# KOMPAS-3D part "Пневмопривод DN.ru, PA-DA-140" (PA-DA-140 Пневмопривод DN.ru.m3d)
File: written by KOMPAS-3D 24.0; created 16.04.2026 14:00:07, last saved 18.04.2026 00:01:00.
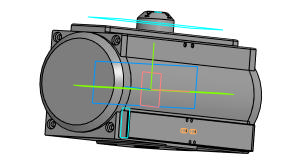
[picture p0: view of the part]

Document properties: Автор: DN.ru; Полное имя файла: C:\Работа\PA-DA-х Пневмопривод DN.ru\140\исходные материалы\PA-DA-140 Пневмопривод DN.ru.m3d

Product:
- Body: Тело 1  | qty 1
    Масса: 67.196724
- Body: Тело 2  | qty 1
    Масса: 67.196724
- Part/product: Пневмопривод DN.ru  | designation PA-DA-140
    Масса: 13
    Раздел спецификации: Прочие изделия
    Примечание: D290-00298

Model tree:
1. Эскиз:1
2. Элемент выдавливания:1
3. Эскиз:2  (with: Ребро.Элемент выдавливания:1)
4. Элемент выдавливания:2
5. Эскиз:3  (with: Ребро.Элемент выдавливания:2)
6. Элемент выдавливания:3  (with: Грань.Элемент выдавливания:2)
     Смещение 1 = -2; Расстояние 2 = 178; Смещение 2 = -2
7. Эскиз:4  (with: Грань.Элемент выдавливания:3)
8. Элемент выдавливания:4
9. Эскиз:6  (with: Ребро.Элемент выдавливания:2)
10. Элемент выдавливания:6
11. Отверстие:2  (with: Грань.Элемент выдавливания:6)
     Глубина выреза = 10; Диаметр отверстия = 5; Угол конуса дна = 120; Расстояние 2 = 4
12. Массив по сетке:2  (with: Отверстие:2)  (3 pattern instances)
     Шаг 1 = 12; Угол раствора = 90; Шаг 2 = 32
13. Массив по сетке:3  (with: Отверстие:2)  (2 pattern instances)
     Шаг 1 = 32; Угол раствора = 90; Шаг 2 = 12
14. Отверстие:3  (with: Грань.Элемент выдавливания:6, Ребро.Элемент выдавливания:6)  (labels: W 1/4'')
     Глубина выреза = 10; Диаметр отверстия = 4.72357; Угол конуса дна = 120; Расстояние 1 = 12; Расстояние 2 = 20
15. W 1/4''  (with: Грань.Отверстие:3, Грань.Элемент выдавливания:6)  (labels: cil5_ex_DIN 477 BSW coarse)
     Длина резьбы = 8; Шаг резьбы = 1.27; Номинальный диаметр резьбы = 6.35
16. Массив по сетке:4  (with: Отверстие:3)  (labels: W 1/4'')  (2 pattern instances)
17. Эскиз:7  (with: Грань.Элемент выдавливания:2)
18. Элемент выдавливания:7
19. Эскиз:8  (with: Грань.Элемент выдавливания:2, Ребро.Элемент выдавливания:2)
20. Элемент выдавливания:8  (with: Грань.Элемент выдавливания:6)
     Расстояние 2 = 4
21. Отверстие:4  (with: Грань.Элемент выдавливания:2)
     Глубина выреза = 7; Диаметр отверстия = 5; Угол конуса дна = 118; Расстояние 1 = 6; Расстояние 2 = 10; Диаметр зенковки = 7; Глубина зенковки = 1; Угол зенковки = 90
22. Массив по сетке:5  (with: Отверстие:4)  (2 pattern instances)
     Шаг 1 = 20; Угол раствора = 90
23. Отверстие:5  (with: Грань.Элемент выдавливания:3)
     Глубина выреза = 10; Диаметр отверстия = 5; Угол конуса дна = 120; Диаметр зенковки = 7; Глубина зенковки = 1; Угол зенковки = 90
24. Массив по сетке:6  (with: Отверстие:5)  (4 pattern instances)
     Угол раствора = 90
25. Фаска:1  (with: Ребро.Элемент выдавливания:4)
     Угол = 45; Длина 1 = 10; Длина 2 = 10
26. Скругление:2  (with: Ребро.Элемент выдавливания:3)
     Радиус = 2
27. Скругление:3  (with: Ребро.Элемент выдавливания:6)
     Радиус = 3
28. Скругление:4  (with: Ребро.Элемент выдавливания:8, Ребро.Элемент выдавливания:2)
     Радиус = 2
29. Скругление:5  (with: Ребро.Элемент выдавливания:6)
     Радиус = 1
30. Смещенная плоскость:1  (with: Грань.Элемент выдавливания:3)
31. Эскиз:9
32. Элемент выдавливания:9  (with: Грань.Фаска:1)
     Расстояние 1 = 35.1642; Смещение 1 = 1
33. Смещенная плоскость:2  (with: Грань.Элемент выдавливания:4)
     Расстояние = 0.5
34. Эскиз:10
35. Элемент выдавливания:10
     Расстояние 1 = 18.4142
36. Эскиз:11  (with: Грань.Элемент выдавливания:4)
37. Элемент выдавливания:11
     Расстояние 1 = 1
38. Эскиз:12  (with: Грань.Элемент выдавливания:11, Ребро.Элемент выдавливания:11)
39. Элемент выдавливания:12  (with: Грань.Элемент выдавливания:4)
     Расстояние 2 = 1
40. Эскиз:13  (with: Грань.Элемент выдавливания:11)
41. Элемент выдавливания:13  (with: Грань.Элемент выдавливания:4)
     Расстояние 2 = 1
42. Скругление:7  (with: Ребро.Элемент выдавливания:11)
     Радиус = 1
43. Скругление:8  (with: Ребро.Элемент выдавливания:8, Ребро.Элемент выдавливания:2)
     Радиус = 2
44. Эскиз:14  (with: Грань.Элемент выдавливания:3)
45. Элемент выдавливания:14  (with: Грань.Фаска:1)
     Расстояние 1 = 46.6414; Смещение 1 = 0.1
46. Эскиз:15  (with: Грань.Элемент выдавливания:3, Ребро.Скругление:2)
47. Элемент выдавливания:15
     Расстояние 2 = 0.1
48. Отверстие:6  (with: Грань.Элемент выдавливания:2, Ребро.Элемент выдавливания:2)
     Глубина выреза = 10; Диаметр отверстия = 8; Угол конуса дна = 118; Расстояние 1 = 10; Расстояние 2 = 10; Диаметр цековки = 15; Глубина цековки = 5
49. Зеркальный массив:1
50. Экземпляр ( 1 )
51. Экземпляр ( 2 )  (with: Отверстие:6)
52. Зеркальный массив:2  (with: Экземпляр ( 1 ), Экземпляр ( 2 ), Отверстие:6)
53. Зеркальный массив:3  (with: Экземпляр ( 1 ), Экземпляр ( 2 ), Зеркальный массив:2, Отверстие:6)
54. Зеркальный массив:4  (with: Экземпляр ( 1 ), Экземпляр ( 2 ), Зеркальный массив:1, Отверстие:6, Зеркальный массив:3, Зеркальный массив:2)
55. Фаска:2  (with: Ребро.Элемент выдавливания:7)
     Угол = 45; Длина 1 = 1; Длина 2 = 1
56. Фаска:3  (with: Ребро.Элемент выдавливания:1)
     Угол = 45; Длина 1 = 10; Длина 2 = 10
57. Смещенная плоскость:3  (with: Грань.Элемент выдавливания:6)
     Расстояние = 5
58. Эскиз:16
59. Элемент выдавливания:16
     Расстояние 2 = 0.1
60. Зеркальный массив:5  (with: Экземпляр ( 1 ), Экземпляр ( 2 ), Элемент выдавливания:16)

Expressions: H/2; -G/2; (E-D-4.5)/2; v2053*2
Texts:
  PA-DA-140
  GOST 26.020 Pr3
